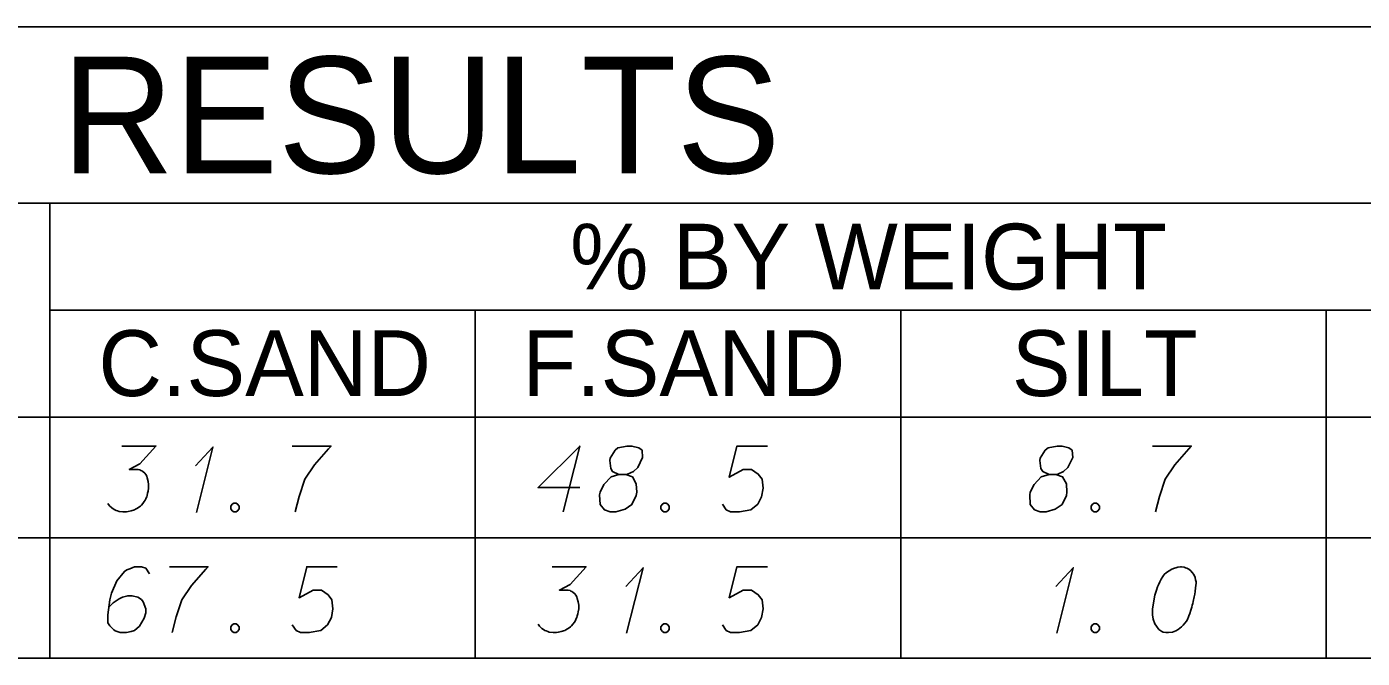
# Model space of a CAD drawing. Extents: x 2074207 to 2076812, y 516372 to 523312.
# Drawn here: x 2076524.4 to 2076621.8, y 516372.3 to 516418.4 of the extents above; entities that cross this region are included whole.
import ezdxf

# ---------------------------------------------------------------- set-up
doc = ezdxf.new("R2010")
doc.units = 0
for name, color, linetype in [('Prop DirtTable_ Soil Test Results - Outline (Major)', 7, 'Continuous'), ('Prop DirtTable_ Soil Test Results - Outline (Minor)', 7, 'Continuous'), ('Prop DirtTable_ Soil Test Results - Tx (Header - Large)', 7, 'Continuous'), ('Prop DirtTable_ Soil Test Results - Tx (Header - Small)', 7, 'Continuous'), ('Prop DirtTable_ Soil Test Results - Tx (Sample Data)', 7, 'Continuous')]:
    doc.layers.add(name, color=color, linetype=linetype)

msp = doc.modelspace()

# ---------------------------------------------------------------- linework, layer by layer
at = {"layer": 'Prop DirtTable_ Soil Test Results - Outline (Major)'}
for p, q in [((2076260.609, 516418.371), (2076811.903, 516418.371)), ((2076260.609, 516389.885), (2076811.903, 516389.885)), ((2076260.609, 516389.885), (2076811.903, 516389.885)), ((2076260.609, 516372.285), (2076811.903, 516372.285))]:
    msp.add_line(p, q, dxfattribs=at)
at = {"layer": 'Prop DirtTable_ Soil Test Results - Outline (Minor)'}
for p, q in [((2076260.609, 516405.485), (2076811.903, 516405.485)), ((2076526.074, 516405.485), (2076526.074, 516381.085)), ((2076526.074, 516397.685), (2076731.93, 516397.685)), ((2076557.094, 516397.685), (2076557.094, 516381.085)), ((2076588.114, 516397.685), (2076588.114, 516381.085)), ((2076619.134, 516381.085), (2076619.134, 516397.685)), ((2076260.609, 516381.085), (2076811.903, 516381.085)), ((2076260.609, 516381.085), (2076811.903, 516381.085)), ((2076526.074, 516381.085), (2076526.074, 516372.285)), ((2076557.094, 516381.085), (2076557.094, 516372.285)), ((2076588.114, 516381.085), (2076588.114, 516372.285)), ((2076619.134, 516372.285), (2076619.134, 516381.085)), ((2076260.609, 516372.285), (2076811.903, 516372.285))]:
    msp.add_line(p, q, dxfattribs=at)
at = {"layer": 'Prop DirtTable_ Soil Test Results - Tx (Sample Data)'}
for points in [[(2076531.339, 516387.767), (2076533.808, 516387.767), (2076532.644, 516386.482), (2076531.868, 516386.066), (2076532.503, 516386.066), (2076532.644, 516386.028), (2076532.714, 516385.99), (2076532.785, 516385.952), (2076532.855, 516385.915), (2076532.997, 516385.801), (2076533.067, 516385.688), (2076533.138, 516385.575), (2076533.173, 516385.461), (2076533.243, 516385.197), (2076533.279, 516384.97), (2076533.279, 516384.856), (2076533.279, 516384.705), (2076533.243, 516384.478), (2076533.208, 516384.327), (2076533.173, 516384.176), (2076533.138, 516384.063), (2076533.102, 516383.987), (2076533.067, 516383.912), (2076533.032, 516383.836), (2076532.961, 516383.723), (2076532.855, 516383.571), (2076532.75, 516383.458), (2076532.679, 516383.382), (2076532.573, 516383.307), (2076532.467, 516383.231), (2076532.326, 516383.156), (2076532.256, 516383.118), (2076532.009, 516383.042), (2076531.797, 516383.004), (2076531.656, 516382.967), (2076531.409, 516382.967), (2076531.127, 516383.004), (2076531.021, 516383.042), (2076530.915, 516383.08), (2076530.809, 516383.118), (2076530.704, 516383.193), (2076530.598, 516383.269), (2076530.421, 516383.42), (2076530.316, 516383.571)], [(2076543.756, 516387.767), (2076546.578, 516387.767), (2076546.401, 516387.578), (2076545.378, 516386.406), (2076544.673, 516385.348), (2076544.249, 516384.1), (2076543.967, 516382.967)], [(2076564.709, 516384.743), (2076561.676, 516384.743), (2076564.709, 516387.767), (2076563.51, 516382.967)], [(2076567.567, 516385.688), (2076568.06, 516385.688), (2076568.202, 516385.726), (2076568.625, 516385.915), (2076568.942, 516386.217), (2076569.295, 516386.935), (2076569.26, 516387.464), (2076569.013, 516387.653), (2076568.519, 516387.767), (2076568.166, 516387.767), (2076567.496, 516387.653), (2076567.284, 516387.464), (2076566.932, 516386.897), (2076566.896, 516386.708), (2076566.967, 516386.141), (2076567.108, 516385.915), (2076567.567, 516385.688), (2076567.002, 516385.537), (2076566.473, 516384.97), (2076566.191, 516384.403), (2076566.156, 516384.214), (2076566.191, 516383.496), (2076566.508, 516383.118), (2076566.932, 516382.967), (2076567.355, 516382.967), (2076568.025, 516383.156), (2076568.519, 516383.496), (2076568.837, 516384.176), (2076568.872, 516384.403), (2076568.837, 516385.008), (2076568.554, 516385.537), (2076568.06, 516385.688)], [(2076578.396, 516387.767), (2076576.174, 516387.767), (2076575.609, 516385.499), (2076576.632, 516386.066), (2076577.232, 516386.066), (2076577.726, 516385.726), (2076578.008, 516385.348), (2076578.079, 516384.705), (2076577.973, 516384.063), (2076577.691, 516383.534), (2076577.197, 516383.118), (2076576.35, 516382.967), (2076575.715, 516382.967), (2076575.398, 516383.118), (2076575.116, 516383.534)], [(2076598.927, 516385.688), (2076599.42, 516385.688), (2076599.562, 516385.726), (2076599.985, 516385.915), (2076600.302, 516386.217), (2076600.655, 516386.935), (2076600.62, 516387.464), (2076600.373, 516387.653), (2076599.879, 516387.767), (2076599.526, 516387.767), (2076598.856, 516387.653), (2076598.644, 516387.464), (2076598.292, 516386.897), (2076598.256, 516386.708), (2076598.327, 516386.141), (2076598.468, 516385.915), (2076598.927, 516385.688), (2076598.362, 516385.537), (2076597.833, 516384.97), (2076597.551, 516384.403), (2076597.516, 516384.214), (2076597.551, 516383.496), (2076597.868, 516383.118), (2076598.292, 516382.967), (2076598.715, 516382.967), (2076599.385, 516383.156), (2076599.879, 516383.496), (2076600.197, 516384.176), (2076600.232, 516384.403), (2076600.197, 516385.008), (2076599.914, 516385.537), (2076599.42, 516385.688)], [(2076606.476, 516387.767), (2076609.298, 516387.767), (2076609.121, 516387.578), (2076608.098, 516386.406), (2076607.393, 516385.348), (2076606.969, 516384.1), (2076606.687, 516382.967)], [(2076536.7, 516386.33), (2076537.97, 516387.691), (2076536.771, 516382.929)], [(2076539.487, 516383.609), (2076539.664, 516383.609), (2076539.769, 516383.534), (2076539.875, 516383.382), (2076539.875, 516383.193), (2076539.769, 516383.042), (2076539.664, 516382.967), (2076539.487, 516382.967), (2076539.381, 516383.042), (2076539.276, 516383.193), (2076539.276, 516383.382), (2076539.381, 516383.534), (2076539.487, 516383.609)], [(2076570.847, 516383.609), (2076571.024, 516383.609), (2076571.129, 516383.534), (2076571.235, 516383.382), (2076571.235, 516383.193), (2076571.129, 516383.042), (2076571.024, 516382.967), (2076570.847, 516382.967), (2076570.741, 516383.042), (2076570.636, 516383.193), (2076570.636, 516383.382), (2076570.741, 516383.534), (2076570.847, 516383.609)], [(2076602.207, 516383.609), (2076602.384, 516383.609), (2076602.489, 516383.534), (2076602.595, 516383.382), (2076602.595, 516383.193), (2076602.489, 516383.042), (2076602.384, 516382.967), (2076602.207, 516382.967), (2076602.101, 516383.042), (2076601.996, 516383.193), (2076601.996, 516383.382), (2076602.101, 516383.534), (2076602.207, 516383.609)], [(2076533.349, 516378.438), (2076533.067, 516378.853), (2076532.75, 516378.967), (2076532.256, 516378.967), (2076531.903, 516378.815), (2076531.691, 516378.74), (2076531.515, 516378.626), (2076530.951, 516377.946), (2076530.563, 516377.039), (2076530.457, 516376.548), (2076530.316, 516375.452), (2076530.316, 516374.885), (2076530.457, 516374.658), (2076530.739, 516374.356), (2076530.845, 516374.28), (2076531.198, 516374.167), (2076531.656, 516374.167), (2076532.009, 516374.242), (2076532.256, 516374.318), (2076532.609, 516374.62), (2076532.961, 516375.225), (2076533.067, 516375.603), (2076533.067, 516375.905), (2076532.891, 516376.397), (2076532.75, 516376.586), (2076532.503, 516376.737), (2076532.079, 516376.85), (2076531.762, 516376.85), (2076531.374, 516376.737), (2076531.127, 516376.623), (2076530.704, 516376.321), (2076530.492, 516376.132), (2076530.386, 516376.019)], [(2076534.796, 516378.967), (2076537.618, 516378.967), (2076537.441, 516378.778), (2076536.418, 516377.606), (2076535.713, 516376.548), (2076535.289, 516375.3), (2076535.007, 516374.167)], [(2076547.036, 516378.967), (2076544.814, 516378.967), (2076544.249, 516376.699), (2076545.272, 516377.266), (2076545.872, 516377.266), (2076546.366, 516376.926), (2076546.648, 516376.548), (2076546.719, 516375.905), (2076546.613, 516375.263), (2076546.331, 516374.734), (2076545.837, 516374.318), (2076544.99, 516374.167), (2076544.355, 516374.167), (2076544.038, 516374.318), (2076543.756, 516374.734)], [(2076562.699, 516378.967), (2076565.168, 516378.967), (2076564.004, 516377.682), (2076563.228, 516377.266), (2076563.863, 516377.266), (2076564.004, 516377.228), (2076564.074, 516377.19), (2076564.145, 516377.152), (2076564.215, 516377.115), (2076564.357, 516377.001), (2076564.427, 516376.888), (2076564.498, 516376.775), (2076564.533, 516376.661), (2076564.603, 516376.397), (2076564.639, 516376.17), (2076564.639, 516376.056), (2076564.639, 516375.905), (2076564.603, 516375.678), (2076564.568, 516375.527), (2076564.533, 516375.376), (2076564.498, 516375.263), (2076564.462, 516375.187), (2076564.427, 516375.112), (2076564.392, 516375.036), (2076564.321, 516374.923), (2076564.215, 516374.771), (2076564.11, 516374.658), (2076564.039, 516374.582), (2076563.933, 516374.507), (2076563.827, 516374.431), (2076563.686, 516374.356), (2076563.616, 516374.318), (2076563.369, 516374.242), (2076563.157, 516374.204), (2076563.016, 516374.167), (2076562.769, 516374.167), (2076562.487, 516374.204), (2076562.381, 516374.242), (2076562.275, 516374.28), (2076562.169, 516374.318), (2076562.064, 516374.393), (2076561.958, 516374.469), (2076561.781, 516374.62), (2076561.676, 516374.771)], [(2076578.396, 516378.967), (2076576.174, 516378.967), (2076575.609, 516376.699), (2076576.632, 516377.266), (2076577.232, 516377.266), (2076577.726, 516376.926), (2076578.008, 516376.548), (2076578.079, 516375.905), (2076577.973, 516375.263), (2076577.691, 516374.734), (2076577.197, 516374.318), (2076576.35, 516374.167), (2076575.715, 516374.167), (2076575.398, 516374.318), (2076575.116, 516374.734)], [(2076608.592, 516378.967), (2076608.522, 516378.967), (2076608.31, 516378.929), (2076608.169, 516378.891), (2076608.063, 516378.853), (2076607.887, 516378.778), (2076607.675, 516378.664), (2076607.499, 516378.551), (2076607.322, 516378.4), (2076607.216, 516378.249), (2076607.111, 516378.06), (2076607.005, 516377.871), (2076606.899, 516377.644), (2076606.828, 516377.493), (2076606.758, 516377.266), (2076606.652, 516376.888), (2076606.546, 516376.321), (2076606.476, 516375.867), (2076606.476, 516375.452), (2076606.511, 516375.149), (2076606.652, 516374.809), (2076606.758, 516374.62), (2076606.934, 516374.393), (2076607.146, 516374.242), (2076607.252, 516374.204), (2076607.463, 516374.167), (2076607.64, 516374.167), (2076607.922, 516374.204), (2076608.169, 516374.28), (2076608.345, 516374.393), (2076608.592, 516374.582), (2076608.698, 516374.696), (2076608.839, 516374.847), (2076608.945, 516374.998), (2076609.015, 516375.112), (2076609.086, 516375.3), (2076609.121, 516375.376), (2076609.192, 516375.565), (2076609.262, 516375.792), (2076609.333, 516376.019), (2076609.368, 516376.17), (2076609.403, 516376.283), (2076609.439, 516376.434), (2076609.509, 516376.775), (2076609.545, 516376.963), (2076609.58, 516377.152), (2076609.615, 516377.417), (2076609.65, 516377.757), (2076609.65, 516377.871), (2076609.615, 516378.022), (2076609.58, 516378.173), (2076609.474, 516378.4), (2076609.368, 516378.551), (2076609.262, 516378.664), (2076609.121, 516378.778), (2076608.98, 516378.853), (2076608.874, 516378.891), (2076608.769, 516378.929), (2076608.592, 516378.967)], [(2076568.06, 516377.53), (2076569.33, 516378.891), (2076568.131, 516374.129)], [(2076599.42, 516377.53), (2076600.69, 516378.891), (2076599.491, 516374.129)], [(2076539.487, 516374.809), (2076539.664, 516374.809), (2076539.769, 516374.734), (2076539.875, 516374.582), (2076539.875, 516374.393), (2076539.769, 516374.242), (2076539.664, 516374.167), (2076539.487, 516374.167), (2076539.381, 516374.242), (2076539.276, 516374.393), (2076539.276, 516374.582), (2076539.381, 516374.734), (2076539.487, 516374.809)], [(2076570.847, 516374.809), (2076571.024, 516374.809), (2076571.129, 516374.734), (2076571.235, 516374.582), (2076571.235, 516374.393), (2076571.129, 516374.242), (2076571.024, 516374.167), (2076570.847, 516374.167), (2076570.741, 516374.242), (2076570.636, 516374.393), (2076570.636, 516374.582), (2076570.741, 516374.734), (2076570.847, 516374.809)], [(2076602.207, 516374.809), (2076602.384, 516374.809), (2076602.489, 516374.734), (2076602.595, 516374.582), (2076602.595, 516374.393), (2076602.489, 516374.242), (2076602.384, 516374.167), (2076602.207, 516374.167), (2076602.101, 516374.242), (2076601.996, 516374.393), (2076601.996, 516374.582), (2076602.101, 516374.734), (2076602.207, 516374.809)]]:
    msp.add_lwpolyline(points, dxfattribs=at)

# ---------------------------------------------------------------- texts
at = {"layer": 'Prop DirtTable_ Soil Test Results - Tx (Header - Large)'}
msp.add_text('SOIL TEST RESULTS', height=8.50001, dxfattribs=at).set_placement((2076465.656, 516407.678))
at = {"layer": 'Prop DirtTable_ Soil Test Results - Tx (Header - Small)'}
for s, height, p in [('% BY WEIGHT', 4.79998, (2076564.009, 516399.196)), ('C.SAND', 4.8, (2076529.618, 516391.42)), ('F.SAND', 4.8, (2076560.529, 516391.42)), ('SILT', 4.8, (2076596.215, 516391.42))]:
    msp.add_text(s, height=height, dxfattribs=at).set_placement(p)

doc.saveas('drawing.dxf')
